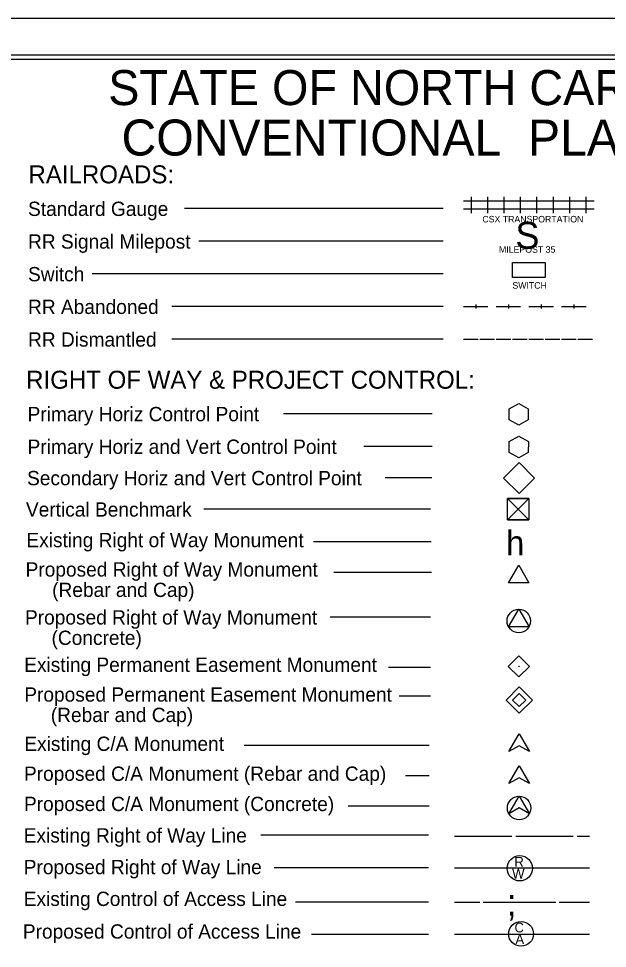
# Model space of a CAD drawing. Extents: x 2078953 to 2080637, y 324331 to 325431.
# Drawn here: x 2079515 to 2079876, y 324862 to 325431 of the extents above; entities that cross this region are included whole.
import ezdxf

# ---------------------------------------------------------------- set-up
doc = ezdxf.new("R2010")
doc.units = 0
for name, color, linetype in [('Default', 7, 'Continuous'), ('Prop ROW Permanent Easement CELL', 7, 'Continuous'), ('Sheet Cutting Line CELL', 7, 'Continuous'), ('Sheet Plot Border Inside CELL', 7, 'Continuous'), ('Sheet Plot Border Outside CELL', 7, 'Continuous'), ('Sheet Symbology CELL', 7, 'Continuous')]:
    doc.layers.add(name, color=color, linetype=linetype)

msp = doc.modelspace()

# ---------------------------------------------------------------- linework, layer by layer
at = {"layer": 'Default'}
for p, q in [((2079821.57, 325188.76), (2079821.57, 325188.76)), ((2079821.56, 325168.8), (2079821.56, 325168.8)), ((2079821.69, 325149.72), (2079821.69, 325149.72)), ((2079821.19, 325130.72), (2079821.19, 325130.72)), ((2079821.66, 325034.5), (2079821.66, 325034.5))]:
    msp.add_line(p, q, dxfattribs=at)
for points in [[(2079821.57, 325182.11), (2079815.77, 325185.4), (2079815.77, 325192.06), (2079821.57, 325195.42), (2079827.36, 325192.13), (2079827.36, 325185.4), (2079821.57, 325182.11)], [(2079827.67, 325137.2), (2079814.7, 325124.23), (2079821.18, 325130.71), (2079827.67, 325124.23), (2079814.7, 325137.2)], [(2079821.18, 325130.71), (2079827.67, 325137.2), (2079814.7, 325137.2), (2079821.18, 325130.71)], [(2079821.18, 325130.71), (2079814.7, 325124.23), (2079827.67, 325124.23), (2079821.18, 325130.71)]]:
    msp.add_lwpolyline(points, dxfattribs=at)
for points in [[(2079815.73, 325172.17), (2079821.59, 325175.44), (2079827.45, 325172.22), (2079827.36, 325165.5), (2079821.5, 325162.09), (2079815.73, 325165.36)], [(2079812.28, 325149.75), (2079821.74, 325159.21), (2079831.21, 325149.74), (2079821.76, 325140.28)], [(2079814.7, 325137.2), (2079827.67, 325137.2), (2079827.67, 325124.23), (2079814.7, 325124.23)], [(2079815.16, 325034.5), (2079821.66, 325041), (2079828.15, 325034.5), (2079821.66, 325028.01)]]:
    msp.add_lwpolyline(points, close=True, dxfattribs=at)
msp.add_circle((2079821.66, 325034.5), 0.126, dxfattribs=at)
at = {"layer": 'Prop ROW Permanent Easement CELL'}
msp.add_line((2079821.83, 325013.9), (2079821.83, 325013.9), dxfattribs=at)
for points in [[(2079821.83, 325021.95), (2079829.89, 325013.89), (2079821.83, 325005.84), (2079813.78, 325013.89)], [(2079821.83, 325017.92), (2079825.86, 325013.89), (2079821.83, 325009.87), (2079817.81, 325013.89)]]:
    msp.add_lwpolyline(points, close=True, dxfattribs=at)
at = {"layer": 'Sheet Cutting Line CELL'}
msp.add_line((2080636.7, 325431.07), (2078952.7, 325431.07), dxfattribs=at)
at = {"layer": 'Sheet Plot Border Inside CELL'}
msp.add_lwpolyline([(2078965.7, 324353.52), (2080632.2, 324353.52), (2080632.2, 325408.62), (2078965.7, 325408.62)], close=True, dxfattribs=at)
at = {"layer": 'Sheet Plot Border Outside CELL'}
msp.add_lwpolyline([(2078952.7, 324331.07), (2080636.7, 324331.07), (2080636.7, 325431.07), (2078952.7, 325431.07)], close=True, dxfattribs=at)
at = {"layer": 'Sheet Symbology CELL'}
for p, q in [((2079792.72, 325312.02), (2079792.72, 325322.02)), ((2079802.72, 325312.02), (2079802.72, 325322.02)), ((2079812.72, 325312.02), (2079812.72, 325322.02)), ((2079822.72, 325312.02), (2079822.72, 325322.02)), ((2079832.72, 325312.02), (2079832.72, 325322.02)), ((2079842.72, 325312.02), (2079842.72, 325322.02)), ((2079852.72, 325312.02), (2079852.72, 325322.02)), ((2079862.72, 325312.02), (2079862.72, 325322.02)), ((2079775.33, 325314.76), (2079616.91, 325314.76)), ((2079787.72, 325319.52), (2079797.72, 325319.52)), ((2079787.72, 325314.52), (2079797.72, 325314.52)), ((2079797.72, 325319.52), (2079807.72, 325319.52)), ((2079797.72, 325314.52), (2079807.72, 325314.52)), ((2079807.72, 325319.52), (2079817.72, 325319.52)), ((2079807.72, 325314.52), (2079817.72, 325314.52)), ((2079817.72, 325319.52), (2079827.72, 325319.52)), ((2079817.72, 325314.52), (2079827.72, 325314.52)), ((2079827.72, 325319.52), (2079837.72, 325319.52)), ((2079827.72, 325314.52), (2079837.72, 325314.52)), ((2079837.72, 325319.52), (2079847.72, 325319.52)), ((2079837.72, 325314.52), (2079847.72, 325314.52)), ((2079847.72, 325319.52), (2079857.72, 325319.52)), ((2079847.72, 325314.52), (2079857.72, 325314.52)), ((2079857.72, 325319.52), (2079867.72, 325319.52)), ((2079857.72, 325314.52), (2079867.72, 325314.52)), ((2079775.33, 325294.76), (2079625.78, 325294.76)), ((2079775.33, 325274.76), (2079560.41, 325274.76)), ((2079775.33, 325254.76), (2079609.16, 325254.76)), ((2079787.72, 325254.76), (2079802.72, 325254.76)), ((2079795.22, 325256.01), (2079795.22, 325253.51)), ((2079807.72, 325254.76), (2079822.72, 325254.76)), ((2079815.22, 325256.01), (2079815.22, 325253.51)), ((2079827.72, 325254.76), (2079842.72, 325254.76)), ((2079835.22, 325256.01), (2079835.22, 325253.51)), ((2079847.72, 325254.76), (2079862.72, 325254.76)), ((2079855.22, 325256.01), (2079855.22, 325253.51)), ((2079775.33, 325234.76), (2079609.16, 325234.76)), ((2079775.33, 325234.76), (2079609.16, 325234.76)), ((2079787.72, 325234.76), (2079796.72, 325234.76)), ((2079797.72, 325234.76), (2079806.72, 325234.76)), ((2079807.72, 325234.76), (2079816.72, 325234.76)), ((2079817.72, 325234.76), (2079826.72, 325234.76)), ((2079827.72, 325234.76), (2079836.72, 325234.76)), ((2079837.72, 325234.76), (2079846.72, 325234.76)), ((2079847.72, 325234.76), (2079856.72, 325234.76)), ((2079857.72, 325234.76), (2079866.72, 325234.76)), ((2079768.63, 325189.14), (2079677.6, 325189.14)), ((2079768.63, 325169.14), (2079726.72, 325169.14)), ((2079768.32, 325149.93), (2079739.77, 325149.93)), ((2079767.63, 325130.71), (2079628.79, 325130.71)), ((2079767.94, 325110.73), (2079695.89, 325110.73)), ((2079768.04, 325091.94), (2079708.31, 325091.94)), ((2079821.56, 325089.33), (2079821.56, 325089.33)), ((2079767.54, 325064.54), (2079706.06, 325064.54)), ((2079821.58, 325062.27), (2079821.58, 325062.27)), ((2079767.62, 325033.85), (2079741.83, 325033.85)), ((2079767.62, 325016.23), (2079748.34, 325016.23)), ((2079815.57, 324982.32), (2079821.82, 324993.12)), ((2079821.82, 324993.12), (2079828.07, 324982.32)), ((2079766.63, 324986.01), (2079653.39, 324986.01)), ((2079821.82, 324985.92), (2079815.57, 324982.32)), ((2079828.07, 324982.32), (2079821.82, 324985.92)), ((2079815.53, 324962.71), (2079821.78, 324973.51)), ((2079821.78, 324973.51), (2079828.03, 324962.71)), ((2079766.73, 324967.47), (2079752.16, 324967.47)), ((2079821.78, 324966.31), (2079815.53, 324962.71)), ((2079828.03, 324962.71), (2079821.78, 324966.31)), ((2079815.53, 324944.2), (2079821.78, 324955)), ((2079821.78, 324955), (2079828.03, 324944.2)), ((2079766.73, 324948.97), (2079717.06, 324948.97)), ((2079821.78, 324947.8), (2079815.53, 324944.2)), ((2079828.03, 324944.2), (2079821.78, 324947.8)), ((2079766.29, 324931.19), (2079663.77, 324931.19)), ((2079782.32, 324930.61), (2079817.32, 324930.61)), ((2079819.82, 324930.61), (2079854.82, 324930.61)), ((2079857.32, 324930.61), (2079864.82, 324930.61)), ((2079766.29, 324911.19), (2079671.76, 324911.19)), ((2079782.32, 324911.06), (2079864.82, 324911.06)), ((2079766.29, 324890.06), (2079684.97, 324890.06)), ((2079782.32, 324890.06), (2079797.78, 324890.06)), ((2079799.78, 324890.06), (2079844.19, 324890.06)), ((2079846.19, 324890.06), (2079864.82, 324890.06)), ((2079766.29, 324870.25), (2079694.64, 324870.25)), ((2079782.32, 324870.63), (2079864.82, 324870.63))]:
    msp.add_line(p, q, dxfattribs=at)
for points in [[(2080619.7, 325406.07), (2079119.7, 325406.07), (2079119.7, 324357.08), (2080619.7, 324357.08)], [(2079817.72, 325281.72), (2079837.72, 325281.72), (2079837.72, 325272.62), (2079817.72, 325272.62)], [(2079815.31, 325085.73), (2079821.56, 325096.53), (2079827.81, 325085.73)], [(2079815.33, 325058.67), (2079821.58, 325069.47), (2079827.83, 325058.67)]]:
    msp.add_lwpolyline(points, close=True, dxfattribs=at)
for centre, radius in [((2079821.58, 325062.26), 7.2), ((2079821.78, 324947.8), 7.2), ((2079822.17, 324910.86), 7.75), ((2079822.97, 324870.73), 7.58)]:
    msp.add_circle(centre, radius, dxfattribs=at)

# ---------------------------------------------------------------- texts
for s, height, p in [('STATE OF NORTH CAROLINA, DIVISION OF HIGHWAYS', 21.419, (2079570.26, 325378.11)), ('CONVENTIONAL  PLAN SHEET SYMBOLS', 22.0323, (2079578.39, 325347.23)), ('RAILROADS:', 11, (2079521.44, 325330.21)), ('Standard Gauge', 8.75, (2079521.16, 325310.23)), ('S', 16.5, (2079819.48, 325290.13)), ('RR Signal Milepost', 8.75, (2079521.16, 325290.23)), ('Switch', 8.75, (2079521.16, 325270.23)), ('RR Abandoned', 8.75, (2079521.16, 325250.23)), ('RR Dismantled', 8.75, (2079521.16, 325230.23)), ('RIGHT OF WAY & PROJECT CONTROL:', 11, (2079520.03, 325204.48)), ('Primary Horiz Control Point', 8.75, (2079520.88, 325184.59)), ('Primary Horiz and Vert Control Point', 8.75, (2079520.88, 325164.59)), ('Secondary Horiz and Vert Control Point', 8.75, (2079520.57, 325145.38)), ('Vertical Benchmark', 8.75, (2079519.88, 325126.16)), ('Existing Right of Way Monument', 8.75, (2079520.19, 325107.45)), ('h', 15, (2079813.79, 325102.55)), ('Proposed Right of Way Monument', 8.75, (2079519.67, 325089.47)), ('     (Rebar and Cap)', 8.75, (2079519.67, 325076.97)), ('Proposed Right of Way Monument', 8.75, (2079519.3, 325060.12)), ('     (Concrete)', 8.75, (2079519.3, 325047.62)), ('Existing Permanent Easement Monument', 8.75, (2079518.82, 325031.13)), ('Proposed Permanent Easement Monument', 8.75, (2079518.86, 325012.9)), ('     (Rebar and Cap)', 8.75, (2079518.86, 325000.4)), ('Existing C/A Monument', 8.75, (2079518.88, 324982.73)), ('Proposed C/A Monument (Rebar and Cap)', 8.75, (2079518.67, 324964.42)), ('Proposed C/A Monument (Concrete)', 8.75, (2079518.67, 324945.91)), ('Existing Right of Way Line', 8.75, (2079518.54, 324926.64)), ('Proposed Right of Way Line', 8.75, (2079518.54, 324907.26)), ('R', 6.08, (2079818.83, 324911.77)), ('W', 6.08, (2079817.45, 324904.61)), ('Existing Control of Access Line', 8.75, (2079518.54, 324887.8)), (';', 16.5, (2079814.11, 324881.88)), ('Proposed Control of Access Line', 8.75, (2079517.99, 324867.82)), ('C', 5.94, (2079818.94, 324871.63)), ('A', 5.94, (2079819.53, 324864.49))]:
    msp.add_text(s, height=height, dxfattribs=at).set_placement(p)
for s, p in [('CSX TRANSPORTATION', (2079799.28, 325306.28)), ('MILEPOST 35', (2079809.47, 325287.71)), ('SWITCH', (2079817.67, 325265.71))]:
    msp.add_text(s, height=4, rotation=360, dxfattribs=at).set_placement(p)

doc.saveas('drawing.dxf')
